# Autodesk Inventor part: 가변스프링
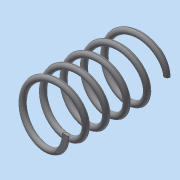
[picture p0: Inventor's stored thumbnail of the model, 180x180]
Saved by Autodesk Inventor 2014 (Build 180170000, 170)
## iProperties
Created: 2024-02
Part Number: 가변스프링
Material: 일반
Document SubType Name: Modeling
Designer: dg
Density: 1 g/cm^3
Appearance: 기본값
Mass: 0.875043 g
Surface Area: 17.7554 cm^2
Volume: 0.875043 cm^3
Author: dg
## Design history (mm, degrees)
sketch "스케치1"
  geometry: L1 (0, 0)-(9, 0); L2 (0, 0)-(0, 28.5); L3 (0, 28.5)-(9, 28.5); C1 r 1 at (9, 0)
  constraints: 6 end point, 2 perpendicular, 1 centre point, 1 coincident, 1 horizontal
  dimensions: "d0" = 9 distance of L1.start L1.end; "d1" = 28.5 distance of L1.start L2.end (derived); "d2" = 1 radius of C1
feature "코일1" pitch "d3" = 10; turns "d5" = 5; dims "d4" = 28.5 (= d1), "d6" = 0, angle "d7" = 90 deg, angle "d8" = 90 deg, "d9" = 0, "d10" = 0
node "작업 평면1"
feature "분할1"
feature "분할2"
node "솔리드1"
other parameters: "d11" = 0
